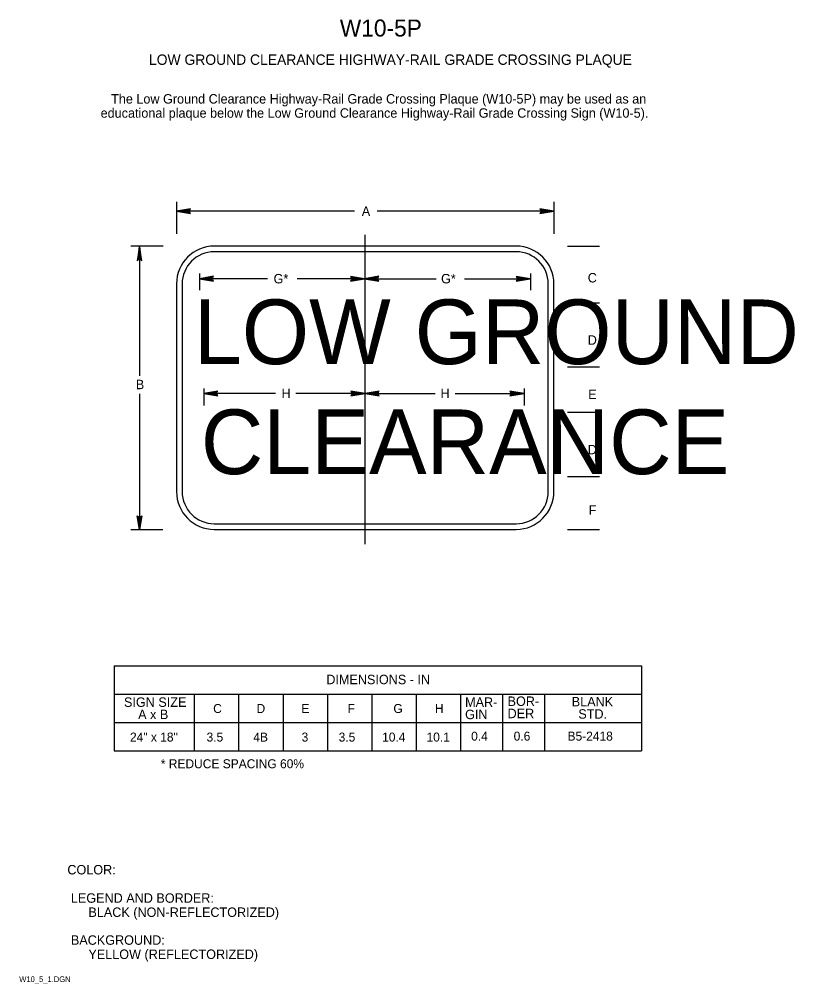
# Model space of a CAD drawing. Extents: x 0.013 to 0.218, y 0.004 to 0.259.
import ezdxf

# ---------------------------------------------------------------- set-up
doc = ezdxf.new("R2010")
doc.units = 0
for name, color, linetype in [('1', 7, 'Continuous'), ('2', 7, 'Continuous'), ('3', 7, 'Continuous')]:
    doc.layers.add(name, color=color, linetype=linetype)

# ---------------------------------------------------------------- blocks, each defined once
blk = doc.blocks.new('RARROW')
at = {"layer": '3'}
for p, q in [((-2.156, 0.285), (-2.2665, 0.384625)), ((-2.2665, 0.384625), (0, 0)), ((0, 0), (-2.2665, -0.379125)), ((-2.156, 0.285), (-2.075625, 0.12075)), ((0, 0), (-2.156, 0.285)), ((-2.14975, -0.2705), (0, 0)), ((-2.075625, 0.12075), (0, 0)), ((0, 0), (-2.074, -0.108)), ((-2.2665, -0.379125), (-2.14975, -0.2705)), ((-2.074, -0.108), (-2.14975, -0.2705))]:
    blk.add_line(p, q, dxfattribs=at)

msp = doc.modelspace()

# ---------------------------------------------------------------- linework, layer by layer
at = {"layer": '1'}
for p, q in [((0.1041, 0.20228), (0.1041, 0.12033)), ((0.06026, 0.19202), (0.06026, 0.18762)), ((0.14796, 0.19202), (0.14796, 0.18762)), ((0.06138, 0.16152), (0.06138, 0.15707)), ((0.14629, 0.16152), (0.14629, 0.15707))]:
    msp.add_line(p, q, dxfattribs=at)
at = {"layer": '3'}
for p, q in [((0.05416, 0.211), (0.05416, 0.2025)), ((0.15416, 0.211), (0.15416, 0.2025)), ((0.10128, 0.2085), (0.05412, 0.2085)), ((0.15416, 0.2085), (0.10731, 0.2085)), ((0.05059, 0.19925), (0.0421, 0.19925)), ((0.04437, 0.19925), (0.04437, 0.16487)), ((0.14416, 0.19925), (0.06416, 0.19925)), ((0.15772, 0.19925), (0.16622, 0.19925)), ((0.14416, 0.19775), (0.06416, 0.19775)), ((0.05416, 0.18925), (0.05416, 0.13425)), ((0.05566, 0.18925), (0.05566, 0.13425)), ((0.07825, 0.19063), (0.06036, 0.19063)), ((0.104, 0.19063), (0.08613, 0.19063)), ((0.10411, 0.19063), (0.123, 0.19063)), ((0.1305, 0.19063), (0.14796, 0.19063)), ((0.15266, 0.13425), (0.15266, 0.18925)), ((0.15416, 0.13425), (0.15416, 0.18925)), ((0.15772, 0.18425), (0.16622, 0.18425)), ((0.15772, 0.16725), (0.16622, 0.16725)), ((0.04437, 0.16018), (0.04437, 0.12412)), ((0.08041, 0.16025), (0.06137, 0.16025)), ((0.10412, 0.16025), (0.08576, 0.16025)), ((0.10412, 0.16025), (0.12265, 0.16025)), ((0.128, 0.16025), (0.14625, 0.16025)), ((0.15772, 0.15525), (0.16622, 0.15525)), ((0.15772, 0.13825), (0.16622, 0.13825)), ((0.06416, 0.12575), (0.14416, 0.12575)), ((0.05056, 0.12414), (0.04206, 0.12414)), ((0.06416, 0.12425), (0.14416, 0.12425)), ((0.15772, 0.12425), (0.16622, 0.12425)), ((0.03762, 0.08812), (0.03762, 0.06563)), ((0.03762, 0.08812), (0.17738, 0.08812)), ((0.17738, 0.08812), (0.17738, 0.06563)), ((0.03762, 0.08063), (0.17738, 0.08063)), ((0.05888, 0.08063), (0.05888, 0.06563)), ((0.07063, 0.08063), (0.07063, 0.06563)), ((0.08238, 0.08063), (0.08238, 0.06563)), ((0.09413, 0.08063), (0.09413, 0.06563)), ((0.10587, 0.08063), (0.10587, 0.06563)), ((0.11763, 0.08063), (0.11763, 0.06563)), ((0.12937, 0.08063), (0.12937, 0.06563)), ((0.1405, 0.08063), (0.1405, 0.06563)), ((0.15163, 0.08063), (0.15163, 0.06563)), ((0.03762, 0.07312), (0.17738, 0.07312)), ((0.03762, 0.06563), (0.17738, 0.06563))]:
    msp.add_line(p, q, dxfattribs=at)
for centre, radius, start, end in [((0.06416, 0.18925), 0.01, 90, 180), ((0.14416, 0.18925), 0.01, 0, 90), ((0.06416, 0.18925), 0.0085, 90, 180), ((0.14416, 0.18925), 0.0085, 0, 90), ((0.06416, 0.13425), 0.01, 180, 270), ((0.06416, 0.13425), 0.0085, 180, 270), ((0.14416, 0.13425), 0.01, 270, 0), ((0.14416, 0.13425), 0.0085, 270, 0)]:
    msp.add_arc(centre, radius, start, end, dxfattribs=at)

# ---------------------------------------------------------------- block references
at = {"layer": '3', "xscale": 0.0016545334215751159}
for p, yscale, rotation in [((0.05412, 0.2085), -0.0016366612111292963, -180), ((0.04437, 0.19912), -0.0016366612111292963, 90.00000000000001), ((0.06025, 0.19063), -0.0016366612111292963, -180), ((0.104, 0.19063), -0.0016366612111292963, -180), ((0.06137, 0.16025), -0.0016366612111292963, -180), ((0.10412, 0.16025), -0.0016366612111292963, -180), ((0.04437, 0.12412), 0.0016366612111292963, -90.00000000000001)]:
    msp.add_blockref('RARROW', p, dxfattribs=dict(at, yscale=yscale, rotation=rotation))
at = {"layer": '3', "xscale": 0.0016545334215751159, "yscale": -0.0016366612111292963}
for p in [(0.15413, 0.2085), (0.104, 0.19063), (0.14788, 0.19063), (0.10412, 0.16025), (0.14625, 0.16025)]:
    msp.add_blockref('RARROW', p, dxfattribs=at)

# ---------------------------------------------------------------- texts
at = {"layer": '1'}
for s, height, p in [('W10-5P', 0.0045, (0.09743, 0.25475)), ('LOW GROUND CLEARANCE HIGHWAY-RAIL GRADE CROSSING PLAQUE', 0.0027503, (0.04688, 0.24725)), ('LOW GROUND', 0.017125, (0.05875, 0.168)), ('CLEARANCE', 0.017125, (0.06062, 0.13887)), ('* REDUCE SPACING 60%', 0.0023752, (0.05, 0.061)), ('COLOR:', 0.0025, (0.02525, 0.03288)), (' LEGEND AND BORDER:', 0.0024998, (0.02525, 0.02538)), ('      BLACK (NON-REFLECTORIZED)', 0.0024998, (0.02525, 0.02163)), (' BACKGROUND:', 0.0024998, (0.02525, 0.01425)), ('      YELLOW (REFLECTORIZED)', 0.0024998, (0.02525, 0.0105)), ('W10_5_1.DGN', 0.0015, (0.0125, 0.00438))]:
    msp.add_text(s, height=height, dxfattribs=at).set_placement(p)
at = {"layer": '2'}
for s, p in [('   The Low Ground Clearance Highway-Rail Grade Crossing Plaque (W10-5P) may be used as an', (0.03406, 0.237)), ('educational plaque below the Low Ground Clearance Highway-Rail Grade Crossing Sign (W10-5).', (0.03406, 0.23325))]:
    msp.add_text(s, height=0.0024998, dxfattribs=at).set_placement(p)
at = {"layer": '3'}
for s, height, p in [('A', 0.0025, (0.10325, 0.20725)), ('G*', 0.0025, (0.07988, 0.18938)), ('G*', 0.0025, (0.12425, 0.18938)), ('C', 0.0025, (0.16312, 0.18963)), ('D', 0.0025, (0.16312, 0.17313)), ('B', 0.0025, (0.04338, 0.16137)), ('H', 0.0025, (0.082, 0.159)), ('H', 0.0025, (0.12412, 0.159)), ('E', 0.0025, (0.16325, 0.15875)), ('D', 0.0025, (0.16312, 0.14413)), ('F', 0.0025, (0.16337, 0.12812)), ('DIMENSIONS - IN', 0.0024998, (0.09386, 0.08325)), ('SIGN SIZE', 0.0025, (0.04025, 0.07725)), ('MAR-', 0.0025, (0.13062, 0.07725)), ('BOR-', 0.0025, (0.14188, 0.0775)), ('BLANK', 0.0025, (0.15888, 0.07737)), ('C', 0.00238, (0.06388, 0.07562)), ('D', 0.00238, (0.07537, 0.07562)), ('E', 0.00238, (0.08725, 0.07562)), ('F', 0.00238, (0.0995, 0.07562)), ('G', 0.00238, (0.11163, 0.07562)), ('H', 0.00238, (0.12262, 0.07562)), ('DER', 0.0025, (0.14188, 0.07425)), ('STD.', 0.0025, (0.16062, 0.07412)), ('A x B', 0.0025, (0.044, 0.074)), ('GIN', 0.0025, (0.13062, 0.074)), ('24" x 18"', 0.002375, (0.04184, 0.06806)), ('3.5', 0.002375, (0.06212, 0.06806)), ('4B', 0.002375, (0.07452, 0.06806)), ('3', 0.00238, (0.08731, 0.06806)), ('3.5', 0.002375, (0.09712, 0.06806)), ('10.4', 0.002375, (0.10864, 0.06806)), ('10.1', 0.002375, (0.1204, 0.06806)), ('0.4', 0.002375, (0.13223, 0.06831)), ('0.6', 0.002375, (0.14349, 0.06831)), ('B5-2418', 0.002375, (0.15776, 0.06831))]:
    msp.add_text(s, height=height, dxfattribs=at).set_placement(p)

doc.saveas('drawing.dxf')
